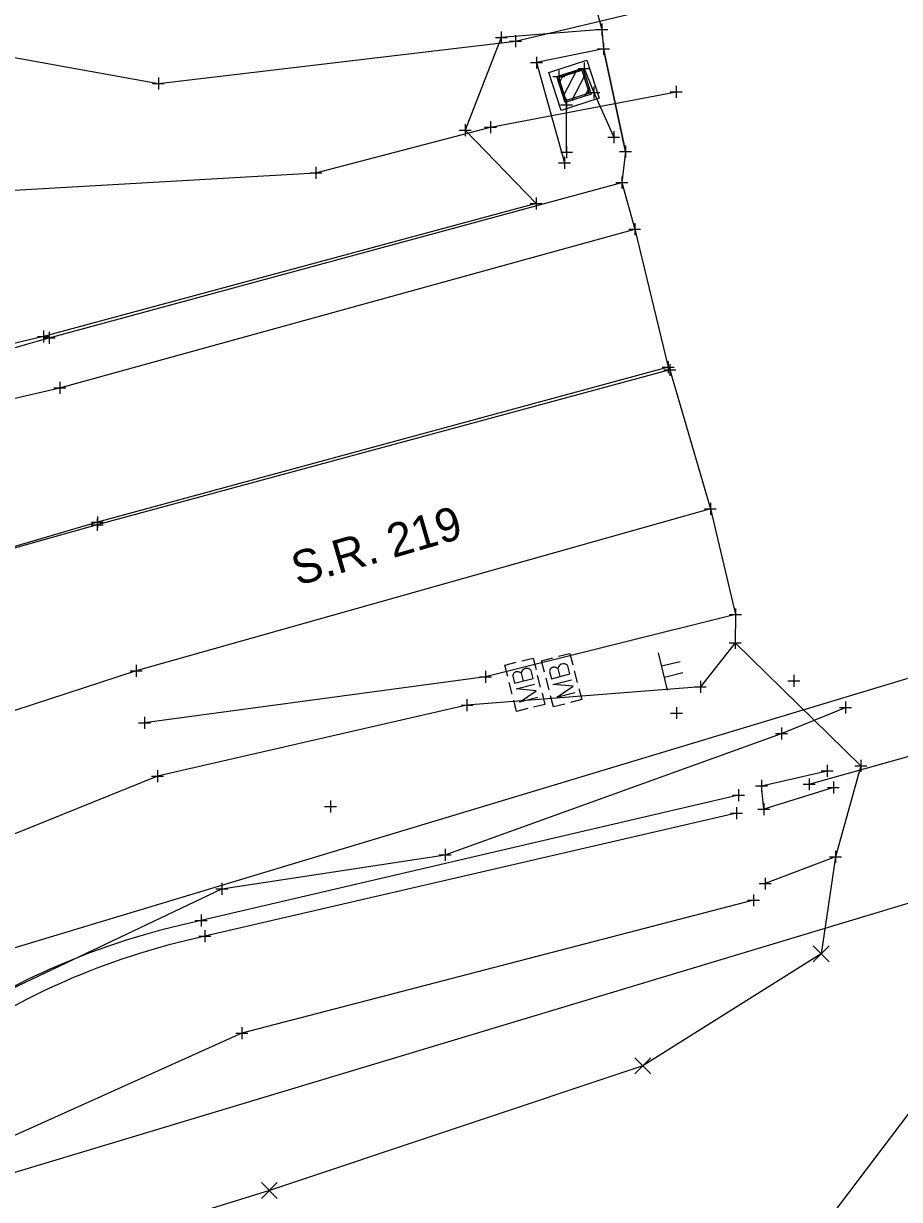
# Model space of a CAD drawing. Extents: x 1391912 to 1392597, y 304167 to 305226.
# Drawn here: x 1392423.8 to 1392497.1, y 304446.3 to 304544.7 of the extents above; entities that cross this region are included whole.
import ezdxf

# ---------------------------------------------------------------- set-up
doc = ezdxf.new("R2010")
doc.units = 0
for name, color, linetype in [('_CIVIL_CONSTRUCTION', 7, 'Continuous'), ('DR_X_Storm_Sewer', 7, 'Continuous'), ('DV_X_Section_VMS_Line', 7, 'Continuous'), ('GE_X_CL_10', 7, 'Continuous'), ('PM_X_CL_Pass_Proh_Lt', 7, 'Continuous'), ('PM_X_Edge_Line', 7, 'Continuous'), ('PV_X_COP', 7, 'Continuous'), ('PV_X_Driveway', 7, 'Continuous'), ('PV_X_EOP', 7, 'Continuous'), ('PV_X_Shoulder_Aggregate', 7, 'Continuous'), ('RW_X_CL', 7, 'Continuous'), ('RW_X_CL_100_Bearings', 7, 'Continuous'), ('RW_X_Esmt_SH', 7, 'Continuous'), ('SV_X_Break_Lines', 7, 'Continuous'), ('SV_X_Terrain_Boundary', 7, 'Continuous'), ('SV_X_Text', 7, 'Continuous'), ('SV_X_Toe_of_Slope', 7, 'Continuous'), ('SV_X_Top_of_Bank', 7, 'Continuous'), ('UT_X_FO', 7, 'Continuous'), ('UT_X_Gas', 7, 'Continuous'), ('UT_X_Overhead_Combined', 7, 'Continuous'), ('UT_X_Sanitary_Line', 7, 'Continuous'), ('UT_X_Sanitary_Pressure_Line', 7, 'Continuous')]:
    doc.layers.add(name, color=color, linetype=linetype)

msp = doc.modelspace()

# ---------------------------------------------------------------- linework, layer by layer
at = {"layer": '_CIVIL_CONSTRUCTION'}
for p, q in [((1392477.722, 304488.934), (1392476.969, 304492.044)), ((1392477.232, 304490.956), (1392478.787, 304491.332)), ((1392477.345, 304490.489), (1392477.345, 304490.489)), ((1392477.458, 304490.023), (1392479.013, 304490.399))]:
    msp.add_line(p, q, dxfattribs=at)
at = {"layer": 'DR_X_Storm_Sewer'}
msp.add_line((1392489.57, 304481.046), (1392543.936, 304496.321), dxfattribs=at)
at = {"layer": 'DV_X_Section_VMS_Line'}
for p, q in [((1392489.915, 304466.202), (1392491.249, 304467.537)), ((1392489.915, 304467.537), (1392491.249, 304466.202)), ((1392474.984, 304456.828), (1392476.317, 304458.163)), ((1392474.984, 304458.163), (1392476.317, 304456.828)), ((1392443.746, 304446.406), (1392445.079, 304447.741)), ((1392443.746, 304447.741), (1392445.079, 304446.406))]:
    msp.add_line(p, q, dxfattribs=at)
at = {"layer": 'GE_X_CL_10'}
for p, q in [((1392468.995, 304538.593), (1392470.13, 304540.807)), ((1392468.648, 304539.67), (1392469.053, 304540.46)), ((1392469.728, 304538.27), (1392470.82, 304540.4)), ((1392470.805, 304538.616), (1392471.167, 304539.323))]:
    msp.add_line(p, q, dxfattribs=at)
for points in [[(1392467.8, 304540.604), (1392470.973, 304541.625), (1392471.995, 304538.452), (1392468.822, 304537.431)], [(1392468.456, 304540.268), (1392470.637, 304540.97), (1392471.339, 304538.789), (1392469.158, 304538.086)], [(1392468.639, 304540.174), (1392470.543, 304540.786), (1392471.156, 304538.883), (1392469.252, 304538.27)]]:
    msp.add_lwpolyline(points, close=True, dxfattribs=at)
at = {"layer": 'PM_X_CL_Pass_Proh_Lt'}
msp.add_lwpolyline([(1392477.913, 304515.713), (1392430.014, 304502.753), (1392385.503, 304490.228)], dxfattribs=at)
at = {"layer": 'PM_X_Edge_Line'}
for p, q in [((1392426.874, 304514.215), (1392474.975, 304527.504)), ((1392397.907, 304507.585), (1392426.874, 304514.215)), ((1392481.304, 304504.095), (1392433.266, 304490.543)), ((1392433.266, 304490.543), (1392413.884, 304484.191))]:
    msp.add_line(p, q, dxfattribs=at)
at = {"layer": 'PV_X_COP'}
msp.add_lwpolyline([(1392477.766, 304515.94), (1392430.048, 304502.968), (1392382.292, 304488.961), (1392368.444, 304485.723)], dxfattribs=at)
at = {"layer": 'PV_X_Driveway'}
msp.add_lwpolyline([(1392361.924, 304622.226), (1392379.437, 304621.741), (1392378.681, 304573.174), (1392378.671, 304570.719), (1392407.236, 304549.982), (1392408.455, 304562.584), (1392422.049, 304560.637), (1392467.938, 304559.975), (1392472.226, 304544.194), (1392463.818, 304543.53), (1392460.796, 304535.788), (1392466.722, 304529.646), (1392425.51, 304518.508), (1392403.575, 304513.307), (1392402.407, 304517.399), (1392406.194, 304521.593), (1392404.009, 304533.278), (1392372.184, 304551.894), (1392366.91, 304535.269), (1392363.313, 304532.598)], dxfattribs=at)
at = {"layer": 'PV_X_EOP'}
for p, q in [((1392425.991, 304518.395), (1392473.892, 304531.391)), ((1392483.409, 304495.247), (1392462.498, 304490.049)), ((1392462.498, 304490.049), (1392433.968, 304486.195))]:
    msp.add_line(p, q, dxfattribs=at)
msp.add_open_spline([(1392360.304, 304539.741), (1392362.492, 304532.06), (1392367.467, 304524.075), (1392381.027, 304515.328), (1392400.296, 304509.631), (1392415.29, 304515.492), (1392425.991, 304518.395)], degree=3, dxfattribs=at)
at = {"layer": 'PV_X_Shoulder_Aggregate'}
for p, q in [((1392483.377, 304492.872), (1392480.468, 304489.203)), ((1392480.468, 304489.203), (1392460.947, 304487.663)), ((1392460.947, 304487.663), (1392435.058, 304481.719)), ((1392435.058, 304481.719), (1392407.471, 304470.577))]:
    msp.add_line(p, q, dxfattribs=at)
at = {"layer": 'RW_X_CL'}
for p, q in [((1392469.387, 304541.115), (1392469.387, 304541.115)), ((1392469.591, 304540.48), (1392469.591, 304540.48)), ((1392470.849, 304539.835), (1392470.849, 304539.835)), ((1392468.946, 304539.222), (1392468.946, 304539.222)), ((1392469.897, 304539.528), (1392469.897, 304539.528)), ((1392469.897, 304539.528), (1392469.897, 304539.528)), ((1392469.897, 304539.528), (1392469.897, 304539.528)), ((1392470.204, 304538.576), (1392470.204, 304538.576)), ((1392470.408, 304537.942), (1392470.408, 304537.942))]:
    msp.add_line(p, q, dxfattribs=at)
at = {"layer": 'RW_X_CL_100_Bearings'}
for p, q in [((1392467.097, 304489.178), (1392466.854, 304490.15)), ((1392467.816, 304488.958), (1392467.565, 304489.927)), ((1392468.871, 304489.759), (1392468.871, 304489.759)), ((1392470.182, 304489.57), (1392469.931, 304490.54)), ((1392464.727, 304488.586), (1392464.484, 304489.558)), ((1392465.788, 304489.378), (1392465.788, 304489.378))]:
    msp.add_line(p, q, dxfattribs=at)
for points in [[(1392465.547, 304491.38), (1392466.488, 304491.615), (1392466.729, 304490.651)], [(1392467.436, 304490.427), (1392467.187, 304491.389), (1392468.126, 304491.632)], [(1392468.613, 304491.759), (1392469.552, 304492.002), (1392469.801, 304491.04)], [(1392464.359, 304490.059), (1392464.118, 304491.023), (1392465.059, 304491.258)], [(1392465.473, 304490.353), (1392465.397, 304490.399), (1392465.351, 304490.426), (1392465.308, 304490.441), (1392465.281, 304490.447), (1392465.226, 304490.46), (1392465.186, 304490.463), (1392465.094, 304490.466), (1392465.057, 304490.457), (1392465.009, 304490.445), (1392464.938, 304490.414), (1392464.883, 304490.374), (1392464.844, 304490.325), (1392464.81, 304490.252), (1392464.798, 304490.197), (1392464.792, 304490.169), (1392464.782, 304490.102), (1392464.932, 304489.503), (1392466.484, 304489.891), (1392466.316, 304490.563), (1392466.246, 304490.637), (1392466.167, 304490.695), (1392466.054, 304490.732), (1392465.935, 304490.741), (1392465.821, 304490.725), (1392465.748, 304490.707), (1392465.681, 304490.664), (1392465.583, 304490.588), (1392465.525, 304490.509), (1392465.473, 304490.353), (1392465.641, 304489.68)], [(1392468.547, 304490.731), (1392468.471, 304490.776), (1392468.425, 304490.803), (1392468.382, 304490.818), (1392468.354, 304490.824), (1392468.299, 304490.836), (1392468.259, 304490.839), (1392468.168, 304490.841), (1392468.131, 304490.831), (1392468.082, 304490.819), (1392468.012, 304490.787), (1392467.958, 304490.747), (1392467.918, 304490.698), (1392467.885, 304490.624), (1392467.874, 304490.569), (1392467.868, 304490.542), (1392467.859, 304490.475), (1392468.014, 304489.877), (1392469.563, 304490.278), (1392469.389, 304490.949), (1392469.318, 304491.022), (1392469.238, 304491.079), (1392469.125, 304491.115), (1392469.006, 304491.123), (1392468.893, 304491.107), (1392468.819, 304491.088), (1392468.753, 304491.044), (1392468.656, 304490.967), (1392468.598, 304490.887), (1392468.547, 304490.731), (1392468.721, 304490.06)], [(1392469.97, 304488.705), (1392468.421, 304488.304), (1392469.825, 304489.266), (1392468.137, 304489.401), (1392469.686, 304489.802)], [(1392466.878, 304488.314), (1392465.326, 304487.927), (1392466.738, 304488.877), (1392465.051, 304489.027), (1392466.603, 304489.414)], [(1392467.223, 304488.675), (1392467.458, 304487.734), (1392466.517, 304487.499)], [(1392470.312, 304489.069), (1392470.555, 304488.13), (1392469.616, 304487.886)], [(1392466.028, 304487.377), (1392465.087, 304487.142), (1392464.852, 304488.083)], [(1392469.129, 304487.76), (1392468.19, 304487.517), (1392467.946, 304488.456)]]:
    msp.add_lwpolyline(points, dxfattribs=at)
at = {"layer": 'RW_X_Esmt_SH'}
for p, q in [((1392472.226, 304544.694), (1392472.226, 304543.694)), ((1392463.818, 304544.03), (1392463.818, 304543.03)), ((1392464.995, 304543.729), (1392464.995, 304542.729)), ((1392471.726, 304544.194), (1392472.726, 304544.194)), ((1392472.226, 304544.194), (1392472.226, 304544.194)), ((1392463.318, 304543.53), (1392464.318, 304543.53)), ((1392463.818, 304543.53), (1392463.818, 304543.53)), ((1392464.495, 304543.229), (1392465.495, 304543.229)), ((1392464.995, 304543.229), (1392464.995, 304543.229)), ((1392472.378, 304543.078), (1392472.378, 304542.078)), ((1392466.756, 304541.927), (1392466.756, 304540.927)), ((1392471.878, 304542.578), (1392472.878, 304542.578)), ((1392472.378, 304542.578), (1392472.378, 304542.578)), ((1392466.256, 304541.427), (1392467.256, 304541.427)), ((1392466.756, 304541.427), (1392466.756, 304541.427)), ((1392468.626, 304540.769), (1392468.626, 304539.769)), ((1392470.255, 304540.927), (1392471.255, 304540.927)), ((1392470.755, 304541.427), (1392470.755, 304540.427)), ((1392470.755, 304540.927), (1392470.755, 304540.927)), ((1392435.126, 304540.178), (1392435.126, 304539.178)), ((1392468.126, 304540.269), (1392469.126, 304540.269)), ((1392468.626, 304540.269), (1392468.626, 304540.269)), ((1392434.626, 304539.678), (1392435.626, 304539.678)), ((1392435.126, 304539.678), (1392435.126, 304539.678)), ((1392471.055, 304538.938), (1392472.055, 304538.938)), ((1392471.555, 304539.438), (1392471.555, 304538.438)), ((1392471.555, 304538.938), (1392471.555, 304538.938)), ((1392477.948, 304538.977), (1392478.948, 304538.977)), ((1392478.448, 304539.477), (1392478.448, 304538.477)), ((1392478.448, 304538.977), (1392478.448, 304538.977)), ((1392468.781, 304537.905), (1392469.781, 304537.905)), ((1392469.281, 304538.405), (1392469.281, 304537.405)), ((1392469.281, 304537.905), (1392469.281, 304537.905)), ((1392460.796, 304536.288), (1392460.796, 304535.288)), ((1392462.408, 304536.026), (1392463.408, 304536.026)), ((1392462.908, 304536.526), (1392462.908, 304535.526)), ((1392462.908, 304536.026), (1392462.908, 304536.026)), ((1392460.296, 304535.788), (1392461.296, 304535.788)), ((1392460.796, 304535.788), (1392460.796, 304535.788)), ((1392472.717, 304535.183), (1392473.717, 304535.183)), ((1392473.217, 304535.683), (1392473.217, 304534.683)), ((1392473.217, 304535.183), (1392473.217, 304535.183)), ((1392468.785, 304533.939), (1392469.785, 304533.939)), ((1392469.285, 304534.439), (1392469.285, 304533.439)), ((1392469.285, 304533.939), (1392469.285, 304533.939)), ((1392473.714, 304533.997), (1392474.714, 304533.997)), ((1392474.214, 304534.497), (1392474.214, 304533.497)), ((1392474.214, 304533.997), (1392474.214, 304533.997)), ((1392468.608, 304533.051), (1392469.608, 304533.051)), ((1392469.108, 304533.551), (1392469.108, 304532.551)), ((1392469.108, 304533.051), (1392469.108, 304533.051)), ((1392447.797, 304532.215), (1392448.797, 304532.215)), ((1392448.297, 304532.715), (1392448.297, 304531.715)), ((1392448.297, 304532.215), (1392448.297, 304532.215)), ((1392473.892, 304531.891), (1392473.892, 304530.891)), ((1392473.392, 304531.391), (1392474.392, 304531.391)), ((1392473.892, 304531.391), (1392473.892, 304531.391)), ((1392466.722, 304530.146), (1392466.722, 304529.146)), ((1392466.222, 304529.646), (1392467.222, 304529.646)), ((1392466.722, 304529.646), (1392466.722, 304529.646)), ((1392474.975, 304528.004), (1392474.975, 304527.004)), ((1392474.475, 304527.504), (1392475.475, 304527.504)), ((1392474.975, 304527.504), (1392474.975, 304527.504)), ((1392425.01, 304518.508), (1392426.01, 304518.508)), ((1392425.491, 304518.395), (1392426.491, 304518.395)), ((1392425.51, 304519.008), (1392425.51, 304518.008)), ((1392425.51, 304518.508), (1392425.51, 304518.508)), ((1392425.991, 304518.895), (1392425.991, 304517.895)), ((1392425.991, 304518.395), (1392425.991, 304518.395)), ((1392477.766, 304516.44), (1392477.766, 304515.44)), ((1392477.913, 304516.213), (1392477.913, 304515.213)), ((1392477.266, 304515.94), (1392478.266, 304515.94)), ((1392477.413, 304515.713), (1392478.413, 304515.713)), ((1392477.766, 304515.94), (1392477.766, 304515.94)), ((1392477.913, 304515.713), (1392477.913, 304515.713)), ((1392426.374, 304514.215), (1392427.374, 304514.215)), ((1392426.874, 304514.715), (1392426.874, 304513.715)), ((1392426.874, 304514.215), (1392426.874, 304514.215)), ((1392481.304, 304504.595), (1392481.304, 304503.595)), ((1392430.048, 304503.468), (1392430.048, 304502.468)), ((1392480.804, 304504.095), (1392481.804, 304504.095)), ((1392481.304, 304504.095), (1392481.304, 304504.095)), ((1392429.514, 304502.753), (1392430.514, 304502.753)), ((1392429.548, 304502.968), (1392430.548, 304502.968)), ((1392430.014, 304503.253), (1392430.014, 304502.253)), ((1392430.014, 304502.753), (1392430.014, 304502.753)), ((1392430.048, 304502.968), (1392430.048, 304502.968)), ((1392483.409, 304495.747), (1392483.409, 304494.747)), ((1392482.909, 304495.247), (1392483.909, 304495.247)), ((1392483.409, 304495.247), (1392483.409, 304495.247)), ((1392482.877, 304492.872), (1392483.877, 304492.872)), ((1392483.377, 304493.372), (1392483.377, 304492.372)), ((1392483.377, 304492.872), (1392483.377, 304492.872)), ((1392433.266, 304491.043), (1392433.266, 304490.043)), ((1392432.766, 304490.543), (1392433.766, 304490.543)), ((1392433.266, 304490.543), (1392433.266, 304490.543)), ((1392461.998, 304490.049), (1392462.998, 304490.049)), ((1392462.498, 304490.549), (1392462.498, 304489.549)), ((1392462.498, 304490.049), (1392462.498, 304490.049)), ((1392480.468, 304489.703), (1392480.468, 304488.703)), ((1392487.795, 304489.708), (1392488.795, 304489.708)), ((1392488.295, 304490.208), (1392488.295, 304489.208)), ((1392488.295, 304489.708), (1392488.295, 304489.708)), ((1392479.968, 304489.203), (1392480.968, 304489.203)), ((1392480.468, 304489.203), (1392480.468, 304489.203)), ((1392460.447, 304487.663), (1392461.447, 304487.663)), ((1392460.947, 304488.163), (1392460.947, 304487.163)), ((1392460.947, 304487.663), (1392460.947, 304487.663)), ((1392492.601, 304487.968), (1392492.601, 304486.968)), ((1392433.968, 304486.695), (1392433.968, 304485.695)), ((1392477.966, 304487.013), (1392478.966, 304487.013)), ((1392478.466, 304487.513), (1392478.466, 304486.513)), ((1392478.466, 304487.013), (1392478.466, 304487.013)), ((1392492.101, 304487.468), (1392493.101, 304487.468)), ((1392492.601, 304487.468), (1392492.601, 304487.468)), ((1392433.468, 304486.195), (1392434.468, 304486.195)), ((1392433.968, 304486.195), (1392433.968, 304486.195)), ((1392487.248, 304485.808), (1392487.248, 304484.808)), ((1392486.748, 304485.308), (1392487.748, 304485.308)), ((1392487.248, 304485.308), (1392487.248, 304485.308)), ((1392493.885, 304483.099), (1392493.885, 304482.099)), ((1392434.558, 304481.719), (1392435.558, 304481.719)), ((1392435.058, 304482.219), (1392435.058, 304481.219)), ((1392435.058, 304481.719), (1392435.058, 304481.719)), ((1392490.578, 304482.163), (1392491.578, 304482.163)), ((1392491.078, 304482.663), (1392491.078, 304481.663)), ((1392491.078, 304482.163), (1392491.078, 304482.163)), ((1392493.385, 304482.599), (1392494.385, 304482.599)), ((1392493.885, 304482.599), (1392493.885, 304482.599)), ((1392485.095, 304480.91), (1392486.095, 304480.91)), ((1392485.595, 304481.41), (1392485.595, 304480.41)), ((1392485.595, 304480.91), (1392485.595, 304480.91)), ((1392489.07, 304481.046), (1392490.07, 304481.046)), ((1392489.57, 304481.546), (1392489.57, 304480.546)), ((1392489.57, 304481.046), (1392489.57, 304481.046)), ((1392491.095, 304480.776), (1392492.095, 304480.776)), ((1392491.595, 304481.276), (1392491.595, 304480.276)), ((1392491.595, 304480.776), (1392491.595, 304480.776)), ((1392483.161, 304480.146), (1392484.161, 304480.146)), ((1392483.661, 304480.646), (1392483.661, 304479.646)), ((1392483.661, 304480.146), (1392483.661, 304480.146)), ((1392449.019, 304479.195), (1392450.019, 304479.195)), ((1392449.519, 304479.695), (1392449.519, 304478.695)), ((1392449.519, 304479.195), (1392449.519, 304479.195)), ((1392483.498, 304479.137), (1392483.498, 304478.137)), ((1392485.282, 304478.971), (1392486.282, 304478.971)), ((1392485.782, 304479.471), (1392485.782, 304478.471)), ((1392485.782, 304478.971), (1392485.782, 304478.971)), ((1392482.998, 304478.637), (1392483.998, 304478.637)), ((1392483.498, 304478.637), (1392483.498, 304478.637)), ((1392458.63, 304475.153), (1392459.63, 304475.153)), ((1392459.13, 304475.653), (1392459.13, 304474.653)), ((1392459.13, 304475.153), (1392459.13, 304475.153)), ((1392491.263, 304474.981), (1392492.263, 304474.981)), ((1392491.763, 304475.481), (1392491.763, 304474.481)), ((1392491.763, 304474.981), (1392491.763, 304474.981)), ((1392485.9, 304473.235), (1392485.9, 304472.235)), ((1392439.948, 304472.301), (1392440.948, 304472.301)), ((1392440.448, 304472.801), (1392440.448, 304471.801)), ((1392440.448, 304472.301), (1392440.448, 304472.301)), ((1392485.4, 304472.735), (1392486.4, 304472.735)), ((1392485.9, 304472.735), (1392485.9, 304472.735)), ((1392484.424, 304471.341), (1392485.424, 304471.341)), ((1392484.924, 304471.841), (1392484.924, 304470.841)), ((1392484.924, 304471.341), (1392484.924, 304471.341)), ((1392438.704, 304470.154), (1392438.704, 304469.154)), ((1392438.204, 304469.654), (1392439.204, 304469.654)), ((1392438.704, 304469.654), (1392438.704, 304469.654)), ((1392438.516, 304468.345), (1392439.516, 304468.345)), ((1392439.016, 304468.845), (1392439.016, 304467.845)), ((1392439.016, 304468.345), (1392439.016, 304468.345)), ((1392441.609, 304460.227), (1392442.609, 304460.227)), ((1392442.109, 304460.727), (1392442.109, 304459.727)), ((1392442.109, 304460.227), (1392442.109, 304460.227))]:
    msp.add_line(p, q, dxfattribs=at)
at = {"layer": 'SV_X_Break_Lines'}
msp.add_line((1392483.498, 304478.637), (1392439.016, 304468.345), dxfattribs=at)
for points in [[(1392469.285, 304533.939), (1392469.281, 304537.905), (1392468.626, 304540.269), (1392470.755, 304540.927), (1392471.555, 304538.938), (1392473.217, 304535.183)], [(1392491.595, 304480.776), (1392485.782, 304478.971), (1392485.595, 304480.91), (1392491.078, 304482.163)]]:
    msp.add_lwpolyline(points, dxfattribs=at)
msp.add_open_spline([(1392439.016, 304468.345), (1392430.216, 304466.362), (1392417.027, 304460.139), (1392402.389, 304445.829), (1392398.078, 304431.165), (1392394.862, 304407.244), (1392393.945, 304370.595), (1392388.074, 304338.516), (1392384.622, 304321.921)], degree=3, dxfattribs=at)
at = {"layer": 'SV_X_Terrain_Boundary'}
msp.add_lwpolyline([(1392467.938, 304559.975), (1392472.226, 304544.194), (1392472.378, 304542.578), (1392474.214, 304533.997), (1392473.892, 304531.391), (1392474.975, 304527.504), (1392477.766, 304515.94), (1392477.913, 304515.713), (1392481.304, 304504.095), (1392483.409, 304495.247), (1392483.377, 304492.872), (1392493.885, 304482.599), (1392491.763, 304474.981), (1392490.582, 304466.869), (1392475.65, 304457.495), (1392444.412, 304447.074), (1392426.356, 304441.443)], dxfattribs=at)
at = {"layer": 'SV_X_Toe_of_Slope'}
msp.add_line((1392483.661, 304480.146), (1392438.704, 304469.654), dxfattribs=at)
msp.add_open_spline([(1392438.704, 304469.654), (1392429.698, 304467.689), (1392416.239, 304461.411), (1392400.705, 304446.97), (1392396.803, 304431.677), (1392391.77, 304407.834), (1392390.546, 304371.012), (1392385.4, 304338.882), (1392382.798, 304322.136)], degree=3, dxfattribs=at)
at = {"layer": 'SV_X_Top_of_Bank'}
for p, q in [((1392484.924, 304471.341), (1392442.109, 304460.227)), ((1392442.109, 304460.227), (1392421.158, 304450.785))]:
    msp.add_line(p, q, dxfattribs=at)
for points in [[(1392474.214, 304533.997), (1392472.378, 304542.578), (1392466.756, 304541.427), (1392469.108, 304533.051)], [(1392493.885, 304482.599), (1392491.763, 304474.981), (1392485.9, 304472.735)]]:
    msp.add_lwpolyline(points, dxfattribs=at)
at = {"layer": 'UT_X_FO'}
for points in [[(1392377.756, 304643.95), (1392378.09, 304635.075), (1392377.398, 304592.311), (1392377.449, 304571.439), (1392382.039, 304557.043), (1392385.784, 304547.258), (1392393.602, 304536.688), (1392410.921, 304530.053), (1392448.297, 304532.215), (1392462.908, 304536.026), (1392478.448, 304538.977)], [(1392385.601, 304634.864), (1392385.071, 304610.61), (1392383.741, 304590.658), (1392382.235, 304574.446), (1392388.982, 304558.09), (1392400.665, 304549.799), (1392415.653, 304543.203), (1392435.126, 304539.678), (1392464.995, 304543.229), (1392483.913, 304547.741)]]:
    msp.add_lwpolyline(points, dxfattribs=at)
at = {"layer": 'UT_X_Gas'}
msp.add_lwpolyline([(1392209.196, 304382.67), (1392248.364, 304369.771), (1392271.268, 304367.909), (1392291.409, 304368.174), (1392295.269, 304374.442), (1392298.637, 304380.681), (1392367.718, 304416.836), (1392378.764, 304440.92), (1392400.627, 304449.06), (1392408.047, 304456.918), (1392440.448, 304472.301), (1392459.13, 304475.153), (1392487.248, 304485.308), (1392492.601, 304487.468)], dxfattribs=at)
at = {"layer": 'UT_X_Overhead_Combined'}
msp.add_line((1392165.204, 304370.85), (1392586.589, 304497.869), dxfattribs=at)
at = {"layer": 'UT_X_Sanitary_Line'}
msp.add_line((1392394.728, 304317.394), (1392509.847, 304469.255), dxfattribs=at)
at = {"layer": 'UT_X_Sanitary_Pressure_Line'}
msp.add_line((1392412.775, 304464.276), (1392581.394, 304515.103), dxfattribs=at)

# ---------------------------------------------------------------- texts
at = {"layer": 'SV_X_Text'}
msp.add_text('S.R. 219', height=2.8, rotation=16.20914, dxfattribs=at).set_placement((1392446.758, 304497.642))

doc.saveas('drawing.dxf')
